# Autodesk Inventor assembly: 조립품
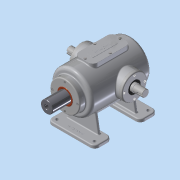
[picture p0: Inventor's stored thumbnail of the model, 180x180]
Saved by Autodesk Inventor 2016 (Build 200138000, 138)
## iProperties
Created: 2018-11
Part Number: 조립품
Material: 일반
Document SubType Name: Assembly
Designer: user
Mass: 8191.27 g
Surface Area: 4241.84 cm^2
Volume: 1855.49 cm^3
Density: 4.41462 g/cm^3
Author: user
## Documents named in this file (15)
- C:\Users\user\Desktop\381121V1004\조립품.iam
- C:\Users\user\Desktop\381121V1004\가변스프링.ipt
- C:\Users\user\Desktop\381121V1004\베어링 6205.ipt
- 베어링 6205.ipt
- C:\Users\user\Desktop\381121V1004\본체.ipt
- C:\Users\user\Desktop\381121V1004\볼트 M4x0.7.ipt
- C:\Users\user\Desktop\381121V1004\부시.ipt
- C:\Users\user\Desktop\381121V1004\상부커버.ipt
- C:\Users\user\Desktop\381121V1004\슬라이드 커버.ipt
- C:\Users\user\Desktop\381121V1004\슬라이드.ipt
- C:\Users\user\Desktop\381121V1004\오일실.ipt
- 오일실.ipt
- C:\Users\user\Desktop\381121V1004\육각머리볼트 M4.ipt
- C:\Users\user\Desktop\381121V1004\축 커버.ipt
- C:\Users\user\Desktop\381121V1004\편심축.ipt
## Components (13 placed, 2 different names)
1. 가변스프링:1
2. M4x0.7:2
3. M4x0.7:4
4. M4x0.7:5
5. M4x0.7:6
6. M4x0.7:1
7. M4x0.7:7
8. M4x0.7:8
9. M4x0.7:9
10. M4x0.7:3
11. M4x0.7:10
12. M4x0.7:11
13. M4x0.7:12
